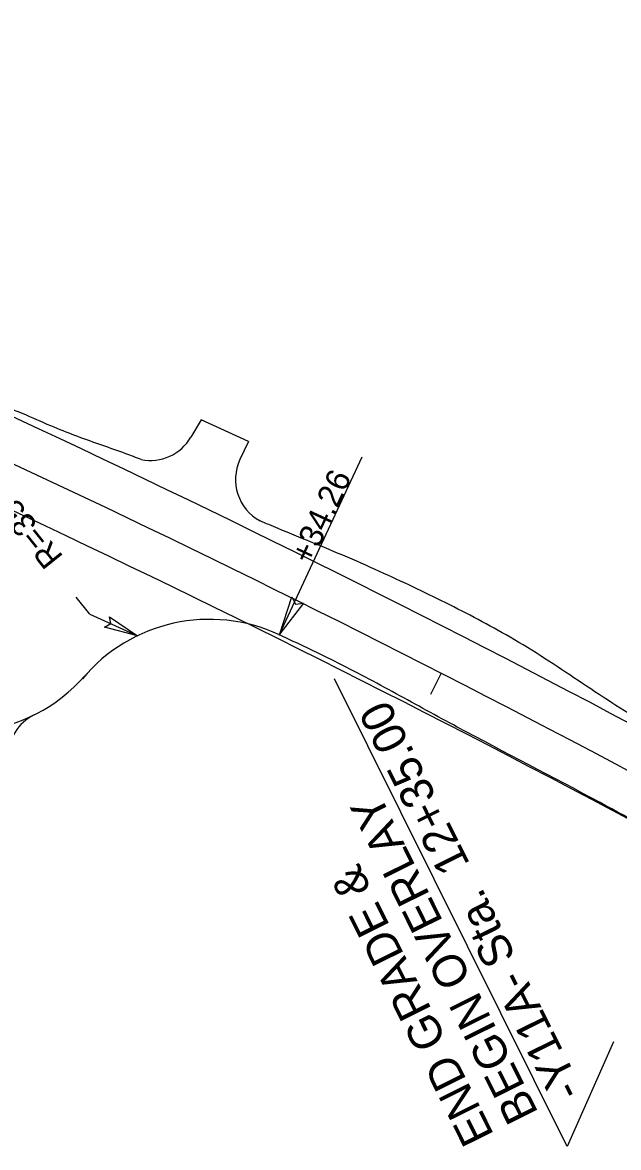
# Model space of a CAD drawing. Extents: x 472216 to 481979, y 489069 to 507339.
# Drawn here: x 475742.8 to 475868.8, y 502468.2 to 502706.2 of the extents above; entities that cross this region are included whole.
import ezdxf

# ---------------------------------------------------------------- set-up
doc = ezdxf.new("R2010")
doc.units = 0
for name, color, linetype in [('Old_Level_12', 7, 'Continuous'), ('Prop Drainage Structure Outlet Berm Ditch 850 10 CELL', 7, 'Continuous'), ('Prop Drainage Structure Pipe CSP 15in', 7, 'Continuous'), ('Prop Drainage Structure Pipe RCP 24in Class III Label', 7, 'Continuous'), ('Sheet Block Revision CELL', 7, 'Continuous'), ('Sheet North Arrow Point CELL', 7, 'Continuous'), ('Sheet PE Seal Cell', 7, 'Continuous'), ('Sheet Plot Border Outside CELL', 7, 'Continuous')]:
    doc.layers.add(name, color=color, linetype=linetype)

msp = doc.modelspace()

# ---------------------------------------------------------------- linework, layer by layer
at = {"layer": 'Old_Level_12'}
for p, q in [((475857.98, 502468.36), (475808.76, 502567.33)), ((475867.77, 502490.52), (475857.98, 502468.36))]:
    msp.add_line(p, q, dxfattribs=at)
at = {"layer": 'Prop Drainage Structure Outlet Berm Ditch 850 10 CELL'}
for points in [[(475802.19, 502583.35), (475797.17, 502576.84), (475799.7, 502584.71), (475800.49, 502583.12)], [(475761.15, 502580.5), (475767.09, 502576.47), (475760.09, 502578.26), (475761.43, 502579.03)]]:
    msp.add_lwpolyline(points, close=True, dxfattribs=at)
at = {"layer": 'Prop Drainage Structure Pipe RCP 24in Class III Label'}
for p, q in [((475780.52, 502622.12), (475778.38, 502618.48)), ((475790.52, 502617.54), (475780.52, 502622.12)), ((475790.52, 502617.54), (475788.75, 502613.78))]:
    msp.add_line(p, q, dxfattribs=at)
for centre, radius, start, end in [((475729.61, 502591.05), 35, 66.5024, 318.8058), ((475769.76, 502623.55), 10, 259.1086, 329.5436), ((475797.8, 502609.52), 10, 154.823, 241.2336), ((475782.28, 502544.94), 35, 64.934, 140.1161), ((475749.64, 502550.75), 10, 116.4345, 179.4213)]:
    msp.add_arc(centre, radius, start, end, dxfattribs=at)
for points in [[(475767.87, 502613.73), (475764.61, 502614.98), (475759.54, 502616.78), (475749.48, 502620.57), (475743.56, 502623.15)], [(475893.53, 502546.91), (475874.64, 502557.84), (475867.39, 502562.3), (475860.29, 502566.99), (475853.18, 502571.68), (475845.92, 502576.15), (475839.15, 502579.89), (475832.27, 502583.43), (475818.29, 502590.07), (475810.52, 502593.49), (475802.68, 502596.74), (475794.84, 502599.98), (475792.99, 502600.76)], [(475884.54, 502530.3), (475864.92, 502541.16), (475834.72, 502557.15), (475828.24, 502560.66), (475821.77, 502564.21), (475808.73, 502571.08), (475797.11, 502576.65)]]:
    msp.add_spline(points, degree=3, dxfattribs=at)
at = {"layer": 'Sheet Block Revision CELL'}
for p, q in [((475797.07, 502576.57), (475814.57, 502614.36)), ((475756.98, 502581.05), (475754.11, 502584.64)), ((475756.98, 502581.05), (475767.09, 502576.48))]:
    msp.add_line(p, q, dxfattribs=at)
at = {"layer": 'Sheet North Arrow Point CELL'}
for centre, radius, start, end in [((473624.13, 501255.38), 2330, 23.81642, 43.37358), ((474546.93, 500058), 2820, 59.03808, 65.52731)]:
    msp.add_arc(centre, radius, start, end, dxfattribs=at)
at = {"layer": 'Sheet PE Seal Cell'}
msp.add_line((475831.32, 502568.52), (475829.04, 502564.07), dxfattribs=at)
at = {"layer": 'Sheet Plot Border Outside CELL'}
for radius in [2829, 2811]:
    msp.add_arc((474546.93, 500058), radius, 59.03808, 65.52731, dxfattribs=at)

# ---------------------------------------------------------------- texts
at = {"layer": 'Old_Level_12'}
for s, p in [('-Y11A- Sta.  12+35.00', (475861.38, 502480.16)), ('BEGIN OVERLAY', (475851.98, 502475.48)), ('END GRADE &', (475842.58, 502470.8))]:
    msp.add_text(s, height=7, rotation=116.4783, dxfattribs=at).set_placement(p)
at = {"layer": 'Prop Drainage Structure Pipe CSP 15in'}
for s, rotation, p in [('+34.26', 65.1243, (475803.76, 502591.35)), ("R=35'", 128.6712, (475751.53, 502593.22))]:
    msp.add_text(s, height=5, rotation=rotation, dxfattribs=at).set_placement(p)

doc.saveas('drawing.dxf')
